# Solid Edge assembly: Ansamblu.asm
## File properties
Author: Ionut
Template: Normal.asm
Last saved by: LAP
Revision: 10
Application: Solid Edge
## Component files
baza.par
ax.par
Interference1.par
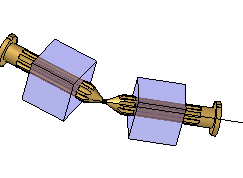
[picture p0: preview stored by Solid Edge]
